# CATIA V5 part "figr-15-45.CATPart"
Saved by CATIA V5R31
Part number: Part1
Bounding box of the stored display mesh (mm): x 2.5 to 37.676, y -21.475 to 20.775, z 0 to 35.904
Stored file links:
  D:\PROJECTS\Project 2021\US EDITION\CATIA V5 6R 2021\Resources\Part Files\c15_catia_v5_6r2021_prt\figr-15-45.CATPart
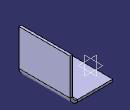
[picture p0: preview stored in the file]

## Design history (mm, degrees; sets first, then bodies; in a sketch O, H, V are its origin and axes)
SheetMetalParameters1: Thickness 2, BendRadius 4, KFactor 0.400515 {= log(min(100,max(20*SheetMetalParameters1.BendRadius,SheetMetalParameters1.Thickness)/SheetMetalParameters1.Thickness))/log(100)/2}, ReliefRadialLength 1, ReliefAxialLength 2, MinimumBendRadius 0
Body1 (main body)
  Sketch1 on xy-plane, origin (0, 0, 0), H (1, 0, 0), V (0, 1, 0)
    line L1 (2.4998, 20.7748) -> (69.1212, 20.7748)
    line L2 (69.1212, 20.7748) -> (69.1212, -21.4753)
    line L3 (69.1212, -21.4753) -> (2.4998, -21.4753)
    line L4 (2.4998, -21.4753) -> (2.4998, 20.7748)
    horizontal: L1 H, L3 H
    vertical: L2 V, L4 V
  Wall1: Thickness 2, Profile Sketch1, OffsetValue 0
  Sketch2 on face of Wall1, origin (0, 0, 2), H (1, 0, 0), V (0, 1, 0)
    line L1 (35.4466, 20.5889) -> (35.4466, -21.306)
    vertical: L1 V
  FlatBend1: Angle 90, Axis Sketch2, FixedPoint vertex [face of Wall1 | face of Wall1 | face of Wall1], KFactor 0.400515 {= log(min(100,max(20*FlatBend1.FlatBendRadius,SheetMetalParameters1.Thickness)/SheetMetalParameters1.Thickness))/log(100)/2}, Radius 4 {= SheetMetalParameters1.BendRadius}
  Unfold1: FoldUnfold_Angles 90, FoldUnfold_FoldUnfoldFaces face of FlatBend1, FoldUnfold_ReferenceFaces face of Wall1
  Fold1: FoldUnfold_Angles 90, FoldUnfold_FoldUnfoldFaces face of FlatBend1, FoldUnfold_ReferenceFaces face of Wall1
